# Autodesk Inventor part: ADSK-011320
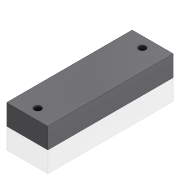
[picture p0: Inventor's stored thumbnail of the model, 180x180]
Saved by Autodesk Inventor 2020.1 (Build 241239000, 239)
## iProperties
Created: 1999-11
Part Number: ADSK-011320
Material: Acier doux
Description: PLT-04,FH,CP,10,060,020,DDDD,BLOCK,MNT,BEARING
Document SubType Name: Modeling
Designer: sspink
Density: 7.86 g/cm^3
Appearance: Metal-Steel(Polish)
Mass: 1465.68 g
Surface Area: 273.063 cm^2
Volume: 186.473 cm^3
Control State: 0
Checked Out: False
Last Check In By: sspink
Last Check In Date: 1999-12-22
Master: False
Shininess: 0.0
Length Units: 11269
Angle Units: 11279
Time Units: 11290
Mass Units: 11283
Length Display Precision: 3
Angle Display Precision: 2
Compacted: True
Dimensions: 50x25x152,5 mm
Mass: 1,466 kg
DocNumber: ADSK-011320.ipt
Folder: 01 - Themengebiete\Simplification\01 - Packaging machine\
VDS_Category: 3D Komponenten
Density: 0.0
Volumn: 0.0
Area: 0.0
PropertySet Name: Model Information
Author: sspink
Revision Number: -
Title: Distance
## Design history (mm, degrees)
node "Solide1"
  node "Extrusion1" dims "d2" = 152.5, "d3" = 0
  node "Hole1" dims "d4" = 8.376, "d5" = 9.525, "d6" = 6.35, "d7" = 60 deg, "d8" = 18, "d9" = 118 deg, "d33" = 15
  node "Hole3" dims "d24" = 8.376, "d25" = 9.525, "d26" = 6.35, "d27" = 60 deg, "d28" = 18, "d29" = 118 deg, "d34" = 15
sketch "Sketch1"
  geometry: L1 (-25, 12.5)-(25, 12.5); L2 (25, 12.5)-(25, -12.5); L3 (25, -12.5)-(-25, -12.5); L4 (-25, -12.5)-(-25, 12.5); 3 further points
  constraints: 8 end point, 2 midpoint, 2 parallel, 1 horizontal, 1 horizontal alignment, 1 perpendicular, 1 vertical alignment
  dimensions: "d0" = 25 distance of L1.end L2.end; "d1" = 50 distance of L2.end L3.end
sketch "Sketch2"
  geometry: L1 (50, 152.5)-(0, 152.5) reference; L2 (0, 0)-(50, 0) reference; L3 (25, 152.5)-(25, 0); L4 (0, 0)-(0, 152.5) reference; L5 (50, 0)-(50, 152.5) reference; L6 (0, 76.25)-(50, 76.25); 2 further points
  constraints: 5 midpoint, 4 end point, 1 point on line, 1 vertical alignment
  dimensions: "d30" = 52 distance from line of L6 point (25, 24.25); "d31" = 52 distance from line of L6 point (25, 128.25) (= d30)
node "Corps solides"
node "Corps surfaciques"
sketch "Sketch4"
  geometry: L1 (0, -152.5)-(50, -152.5) reference; L2 (50, 0)-(0, 0) reference; L3 (25, 0)-(25, -152.5); 2 further points
  constraints: 2 end point, 2 midpoint, 2 point on line
  dimensions: "d22" = 12.7 distance from line of point (25, -139.8) L1 (= d23); "d23" = 12.7 distance from line of point (25, -12.7) L2
